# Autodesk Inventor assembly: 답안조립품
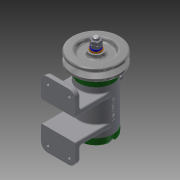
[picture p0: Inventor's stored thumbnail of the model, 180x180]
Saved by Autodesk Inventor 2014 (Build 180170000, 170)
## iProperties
Created: 2017-02
Part Number: 답안조립품
Document SubType Name: Assembly
Designer: owner
Author: owner
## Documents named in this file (16)
- C:\Users\owner\Desktop\470207V1005\답안조립품.iam
- C:\Users\owner\Desktop\470207V1005\본체.ipt
- C:\Users\owner\Desktop\470207V1005\베어링 15 x 32 x 9.ipt
- C:\Users\owner\Desktop\470207V1005\축.ipt
- C:\Users\owner\Desktop\470207V1005\뒤커버.ipt
- C:\Users\owner\Desktop\470207V1005\볼트 M4 x 12.ipt
- C:\Users\owner\Desktop\470207V1005\앞커버.ipt
- C:\Users\owner\Desktop\470207V1005\오일 실 15 25 7.ipt
- C:\Users\owner\Desktop\470207V1005\키 3 x 3 x 12.ipt
- C:\Users\owner\Desktop\470207V1005\V벨트풀리.ipt
- C:\Users\owner\Desktop\470207V1005\스프링와셔 8.ipt
- C:\Users\owner\Desktop\470207V1005\와셔 8x17.ipt
- C:\Users\owner\Desktop\470207V1005\너트 M 8.ipt
- C:\Users\owner\Desktop\470207V1005\니플 M 6 x 0.75.ipt
- C:\Users\owner\Desktop\470207V1005\볼트 M 6 x 8.ipt
- C:\Users\owner\Desktop\470207V1005\와셔 6x11.5.ipt
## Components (11 placed, 3 different names)
1. KS B 2023 6002 - 15 x 32 x 9:1
2. KS B 2023 6002 - 15 x 32 x 9:2
3. V벨트풀리:1 — 각도:2
4. ISO 4762 M4 x 12:1
5. ISO 4762 M4 x 12:2
6. ISO 4762 M4 x 12:3
7. ISO 4762 M4 x 12:4
8. ISO 4762 M4 x 12:5
9. ISO 4762 M4 x 12:6
10. ISO 4762 M4 x 12:7
11. ISO 4762 M4 x 12:8
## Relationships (1: Angle 1)
- 각도:2 [Angle]: V벨트풀리:1
